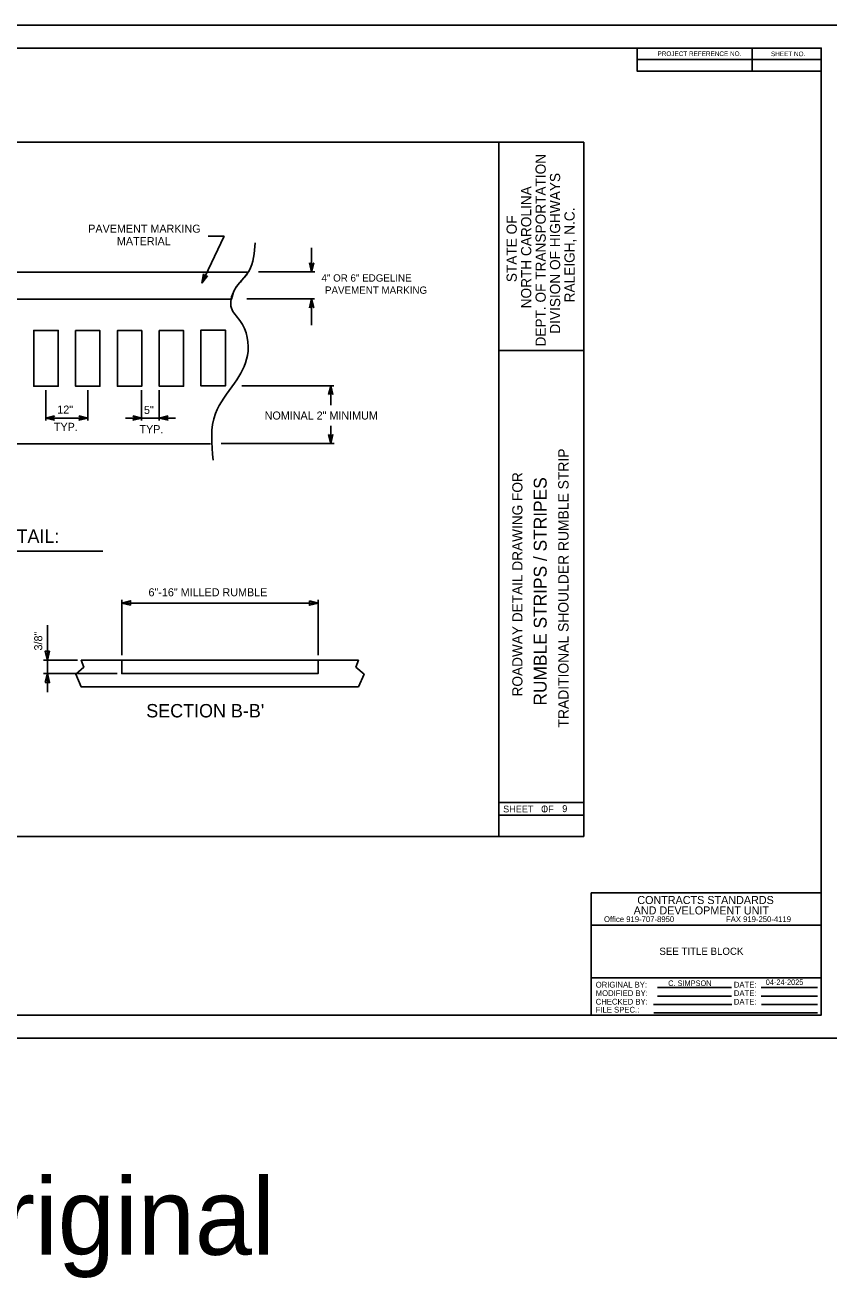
# Model space of a CAD drawing. Extents: x 1994737 to 2001433, y 527447 to 529360.
# Drawn here: x 1995696 to 1996750, y 527488 to 529114 of the extents above; entities that cross this region are included whole.
import ezdxf

# ---------------------------------------------------------------- set-up
doc = ezdxf.new("R2010")
doc.units = 0
for name, color, linetype in [('Default', 7, 'Continuous'), ('GSBWFILL', 7, 'Continuous'), ('Old_Level_1', 7, 'Continuous'), ('Old_Level_40', 7, 'Continuous'), ('Old_Level_60', 7, 'Continuous'), ('Prop Mkg Solid Yel Skip LT', 7, 'Continuous'), ('Prop Sign E Yield Sign Ahead CELL', 7, 'Continuous'), ('Prop Support Two', 7, 'Continuous')]:
    doc.layers.add(name, color=color, linetype=linetype)

# ---------------------------------------------------------------- blocks, each defined once
blk = doc.blocks.new('TERM2')
at = {"layer": 'Default'}
for p, q in [((-6.25, 1.563), (0, 0)), ((-4.687, 0), (-6.25, 1.563)), ((0, 0), (-6.25, -1.563)), ((-6.25, -1.563), (-4.687, 0))]:
    blk.add_line(p, q, dxfattribs=at)
blk = doc.blocks.new('TERM')
at = {"layer": 'Default'}
blk.add_lwpolyline([(-6.25, 1.563), (0, 0), (-6.25, -1.563)], close=True, dxfattribs=at)

msp = doc.modelspace()

# ---------------------------------------------------------------- linework, layer by layer
at = {"layer": 'Default'}
for p, q in [((1995954.6, 528840.3), (1995925.3, 528779.3)), ((1995933.9, 528840.3), (1995954.6, 528840.3)), ((1996068, 528824.8), (1996068, 528793.8)), ((1995178.8, 528793.5), (1995986.2, 528793.5)), ((1995985.9, 528793.5), (1995179.6, 528793.5)), ((1995998.9, 528793.8), (1996072.1, 528793.8)), ((1995201.2, 528758.5), (1995964.5, 528758.5)), ((1995201.7, 528758.5), (1995963.8, 528758.5)), ((1995983.9, 528758.9), (1996071.9, 528758.9)), ((1996068, 528758.8), (1996068, 528724.6)), ((1995723.1, 528640.4), (1995723.1, 528600.7)), ((1995777.4, 528640.4), (1995777.4, 528600.7)), ((1995847.4, 528640.4), (1995847.4, 528600.7)), ((1995870.1, 528640.4), (1995870.1, 528600.7)), ((1995977.2, 528646), (1996096.8, 528646)), ((1996092.8, 528620.9), (1996092.8, 528646)), ((1995722.9, 528604.1), (1995777.4, 528604.1)), ((1995826.6, 528604.1), (1995891.4, 528604.1)), ((1996092.8, 528571.2), (1996092.8, 528594)), ((1995228.8, 528570.4), (1995936.7, 528570.4)), ((1995950.5, 528571.2), (1996097.2, 528571.2)), ((1995534.7, 528431.2), (1995796.9, 528431.2)), ((1995821.5, 528296.3), (1995821.5, 528367.9)), ((1995821.5, 528364), (1996076.6, 528364)), ((1996076.6, 528296.3), (1996076.6, 528367.9)), ((1995725, 528289.8), (1995725, 528335.2)), ((1995764, 528289.8), (1995719.9, 528289.8)), ((1995725, 528272.4), (1995725, 528289.8)), ((1995772.4, 528280.9), (1995761.8, 528271.6)), ((1995772.4, 528280.9), (1995761.8, 528271.6)), ((1995769.1, 528289.8), (1995772.4, 528280.9)), ((1995769.1, 528289.8), (1995772.4, 528280.9)), ((1995821.5, 528289.8), (1995769.1, 528289.8)), ((1995769.1, 528289.8), (1995769.1, 528289.8)), ((1995769.1, 528289.8), (1995772.4, 528280.9)), ((1995772.4, 528280.9), (1995769.1, 528289.8)), ((1995769.1, 528289.8), (1995821.5, 528289.8)), ((1995821.5, 528289.8), (1995821.5, 528272.4)), ((1995821.5, 528272.4), (1995821.5, 528289.8)), ((1995821.5, 528289.8), (1995954.8, 528289.8)), ((1995954.8, 528289.8), (1996128.7, 528289.8)), ((1996076.3, 528289.8), (1996076.3, 528272.4)), ((1996076.3, 528289.8), (1996128.7, 528289.8)), ((1996076.3, 528288.1), (1996076.3, 528289.8)), ((1996076.3, 528272.4), (1996076.3, 528288.1)), ((1996128.7, 528289.8), (1996125.4, 528280.9)), ((1996128.7, 528289.8), (1996125.4, 528280.9)), ((1996125.4, 528280.9), (1996136, 528271.6)), ((1996125.4, 528280.9), (1996136, 528271.6)), ((1995815.7, 528272.4), (1995719.9, 528272.4)), ((1995725, 528272.4), (1995725, 528248.3)), ((1995761.8, 528271.6), (1995769.1, 528255)), ((1995761.8, 528271.6), (1995769.1, 528255)), ((1995821.5, 528272.4), (1995943.7, 528272.4)), ((1995943.7, 528272.4), (1995821.5, 528272.4)), ((1995943.7, 528272.4), (1996076.3, 528272.4)), ((1995943.7, 528272.4), (1996076.3, 528272.4)), ((1996136, 528271.6), (1996128.7, 528255)), ((1996136, 528271.6), (1996128.7, 528255)), ((1995769.1, 528255), (1995949.6, 528255)), ((1995769.1, 528255), (1995949.6, 528255)), ((1995949.6, 528255), (1996128.7, 528255)), ((1996128.7, 528255), (1995949.6, 528255))]:
    msp.add_line(p, q, dxfattribs=at)
for points in [[(1995003.5, 528962), (1996421.2, 528962), (1996421.2, 528061), (1995003.5, 528061)], [(1995924.4, 528718.1), (1995956, 528718.1), (1995956, 528645.7), (1995924.4, 528645.7)], [(1995707.4, 528717.7), (1995739.1, 528717.7), (1995739.1, 528645.3), (1995707.4, 528645.3)], [(1995761.6, 528717.6), (1995793.3, 528717.6), (1995793.3, 528645.2), (1995761.6, 528645.2)], [(1995815.9, 528717.6), (1995847.6, 528717.6), (1995847.6, 528645.2), (1995815.9, 528645.2)], [(1995870.2, 528717.6), (1995901.9, 528717.6), (1995901.9, 528645.2), (1995870.2, 528645.2)], [(1996076.3, 528289.8), (1996128.7, 528289.8), (1996125.4, 528280.9), (1996136, 528271.6), (1996128.7, 528255), (1995769.1, 528255), (1995761.8, 528271.6), (1995772.4, 528280.9), (1995769.1, 528289.8), (1995821.5, 528289.8), (1995821.5, 528272.4), (1996076.3, 528272.4)]]:
    msp.add_lwpolyline(points, close=True, dxfattribs=at)
for points in [[(1995924.4, 528645.7), (1995956, 528645.7), (1995956, 528718.1), (1995924.4, 528718.1), (1995924.4, 528645.7)], [(1995707.4, 528645.3), (1995739.1, 528645.3), (1995739.1, 528717.7), (1995707.4, 528717.7), (1995707.4, 528645.3)], [(1995761.6, 528645.2), (1995793.3, 528645.2), (1995793.3, 528717.6), (1995761.6, 528717.6), (1995761.6, 528645.2)], [(1995815.9, 528645.2), (1995847.6, 528645.2), (1995847.6, 528717.6), (1995815.9, 528717.6), (1995815.9, 528645.2)], [(1995870.2, 528645.2), (1995901.9, 528645.2), (1995901.9, 528717.6), (1995870.2, 528717.6), (1995870.2, 528645.2)]]:
    msp.add_lwpolyline(points, dxfattribs=at)
for points in [[(1995994.6, 528831.6), (1995986.7, 528795.1), (1995967.9, 528770.3), (1995963.9, 528746.6), (1995974.8, 528730.7), (1995984.7, 528685.1), (1995967.9, 528649.5), (1995943.1, 528609.9), (1995940, 528549.3)], [(1995963.8, 528758.5), (1995967.9, 528770.3), (1995969.7, 528773.5), (1995971.9, 528776.4), (1995976.7, 528781.9), (1995981.7, 528787.4), (1995983.9, 528790.4), (1995985.9, 528793.5)]]:
    msp.add_spline(points, degree=3, dxfattribs=at)
at = {"layer": 'GSBWFILL'}
for p, q in [((1996749.7, 529114.1), (1994737.1, 529114.1)), ((1994737.1, 527799.4), (1996749.7, 527799.4))]:
    msp.add_line(p, q, dxfattribs=at)
at = {"layer": 'Old_Level_40'}
for p, q in [((1996639.7, 529084.1), (1996639.7, 529054.3)), ((1996490.3, 529069.2), (1996729.4, 529069.2))]:
    msp.add_line(p, q, dxfattribs=at)
msp.add_lwpolyline([(1996490.3, 529084.2), (1996729.4, 529084.2), (1996729.4, 529054.3), (1996490.3, 529054.3)], close=True, dxfattribs=at)
at = {"layer": 'Old_Level_60'}
for p, q in [((1996729.4, 527988), (1996430.6, 527988)), ((1996430.6, 527988), (1996430.6, 527946.1)), ((1996729.4, 527829.3), (1996729.4, 527988)), ((1996430.6, 527866.7), (1996430.6, 527946.1)), ((1996430.6, 527946.1), (1996729.4, 527946.1)), ((1996729.4, 527877.7), (1996430.6, 527877.7)), ((1996430.6, 527866.7), (1996430.6, 527829.3)), ((1996516.9, 527864.9), (1996612.8, 527864.9)), ((1996651.4, 527864.9), (1996724.4, 527864.9)), ((1996511.7, 527842.8), (1996613.2, 527842.8)), ((1996516.9, 527853.8), (1996612.8, 527853.8)), ((1996651.4, 527853.8), (1996724.4, 527853.8)), ((1996651.9, 527842.8), (1996724.4, 527842.8)), ((1996430.6, 527829.3), (1996729.4, 527829.3)), ((1996512, 527832.3), (1996724.4, 527832.3))]:
    msp.add_line(p, q, dxfattribs=at)
msp.add_lwpolyline([(1996310.8, 528691.7), (1996421.2, 528691.7), (1996421.2, 528962), (1996310.8, 528962), (1996310.8, 528061), (1996421.2, 528061), (1996421.2, 528088.6), (1996310.8, 528088.6), (1996310.8, 528105.2), (1996421.2, 528105.2)], dxfattribs=at)
at = {"layer": 'Prop Sign E Yield Sign Ahead CELL'}
msp.add_lwpolyline([(1996729.4, 529084.2), (1994936.7, 529084.2), (1994936.7, 527829.3), (1996729.4, 527829.3)], close=True, dxfattribs=at)
at = {"layer": 'Prop Support Two'}
msp.add_line((1996749.7, 529114.1), (1996749.7, 529114.1), dxfattribs=at)

# ---------------------------------------------------------------- block references
at = {"layer": 'Default'}
for name, p, xscale, yscale, rotation in [('TERM2', (1996068, 528793.8), 1.8556685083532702, 1.8556685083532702, -89.99999999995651), ('TERM2', (1995925.3, 528779.3), 1.8556685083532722, 1.8556685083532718, -115.63251036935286), ('TERM2', (1996068, 528758.8), 1.8556685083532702, 1.8556685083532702, 90.00000000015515), ('TERM2', (1996092.8, 528646), 1.8556685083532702, 1.8556685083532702, 90.00000000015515), ('TERM2', (1995722.9, 528604.1), 1.8556685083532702, 1.8556685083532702, 179.99999999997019), ('TERM2', (1995777.4, 528604.1), 1.8556685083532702, 1.8556685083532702, -2.9817700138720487e-11), ('TERM2', (1995847.6, 528604.1), 1.8556685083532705, 1.8556685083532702, -0.009516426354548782), ('TERM2', (1995870.2, 528604.1), 1.855668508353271, 1.8556685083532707, -179.75274341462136), ('TERM2', (1996092.8, 528571.2), 1.8556685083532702, 1.8556685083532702, -89.99999999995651), ('TERM', (1995821.5, 528364), 1.8556685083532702, 1.8556685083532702, 179.9999999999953), ('TERM', (1996076.6, 528364), 1.8556685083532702, 1.8556685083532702, -4.686499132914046e-12), ('TERM', (1995725, 528289.8), 1.8556685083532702, 1.8556685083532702, -90.0000000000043), ('TERM', (1995725, 528272.4), 1.8556685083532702, 1.8556685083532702, 89.99999999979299)]:
    msp.add_blockref(name, p, dxfattribs=dict(at, xscale=xscale, yscale=yscale, rotation=rotation))

# ---------------------------------------------------------------- texts
for s, height, rotation, p in [('PAVEMENT MARKING', 10.438, 360, (1995778.1, 528844.6)), ('MATERIAL', 10.44, 360, (1995815.3, 528828.4)), ('4" OR 6" EDGELINE', 9.489, 360, (1996080.8, 528781.1)), ('PAVEMENT MARKING', 9.489, 360, (1996085.3, 528765.3)), ('12"', 10.44, 360, (1995737.9, 528609.8)), ('5"', 10.44, 360, (1995850.4, 528609.3)), ('NOMINAL 2" MINIMUM', 10.438, 360, (1996007, 528602.1)), ('TYP.', 10.44, 360, (1995733.5, 528587.4)), ('TYP.', 10.44, 360, (1995844.6, 528584.4)), ('MILLING DETAIL:', 17.397, 0, (1995553.2, 528442)), ('6"-16" MILLED RUMBLE', 10.438, 0, (1995856.3, 528372.7)), ('3/8"', 10.44, 90.0002, (1995718.4, 528302.4)), ("SECTION B-B'", 17.397, 0, (1995853.4, 528215.5)), ('SHEET 1 - original', 99.727, 0, (1994916, 527518.1))]:
    msp.add_text(s, height=height, rotation=rotation, dxfattribs=at).set_placement(p)
for s, p in [('C. SIMPSON', (1996530.7, 527867)), ('04-24-2025', (1996657.3, 527868.3))]:
    msp.add_text(s, height=7.14, dxfattribs=at).set_placement(p)
at = {"layer": 'Old_Level_1'}
for s, height, p in [('TRADITIONAL SHOULDER RUMBLE STRIP', 13.461, (1996401.4, 528202.4)), ('RUMBLE STRIPS / STRIPES', 16.826, (1996373, 528230.9))]:
    msp.add_text(s, height=height, rotation=90, dxfattribs=at).set_placement(p)
msp.add_text('1      9', height=8.97, dxfattribs=at).set_placement((1996366.5, 528092.6))
at = {"layer": 'Old_Level_60'}
for s, height, rotation, p in [('DEPT. OF TRANSPORTATION', 13.245, 90, (1996371.8, 528696.9)), ('DEPT. OF TRANSPORTATION', 13.245, 90, (1996371.8, 528696.9)), ('DIVISION OF HIGHWAYS', 13.245, 90, (1996390.5, 528713.5)), ('DIVISION OF HIGHWAYS', 13.245, 90, (1996390.5, 528713.5)), ('NORTH CAROLINA', 13.245, 90, (1996353, 528746.4)), ('NORTH CAROLINA', 13.245, 90, (1996353, 528746.4)), ('STATE OF', 13.24, 90, (1996334.2, 528780.4)), ('STATE OF', 13.24, 90, (1996334.2, 528780.4)), ('RALEIGH, N.C.', 13.245, 90, (1996409.3, 528754.2)), ('RALEIGH, N.C.', 13.245, 90, (1996409.3, 528754.2)), ('ROADWAY DETAIL DRAWING FOR', 13.236, 90, (1996341.6, 528242.7)), ('SEE TITLE BLOCK', 9.406, 0.0008, (1996519.3, 527907.3))]:
    msp.add_text(s, height=height, rotation=rotation, dxfattribs=at).set_placement(p)
for s, height, p in [('SHEET   OF', 8.83, (1996316.5, 528092.2)), ('SHEET   OF', 8.83, (1996316.5, 528092.2)), ('AND DEVELOPMENT UNIT', 10.457, (1996485.9, 527959.8)), ('CONTRACTS STANDARDS', 10.457, (1996490.6, 527973.3)), ('Office 919-707-8950', 7.469, (1996447.4, 527949.9)), ('FAX 919-250-4119', 7.469, (1996605.7, 527949.9)), ('ORIGINAL BY:', 7.469, (1996436.6, 527864.9)), ('DATE:', 7.47, (1996615.9, 527864.9)), ('MODIFIED BY:', 7.469, (1996436.6, 527853.9)), ('DATE:', 7.47, (1996615.9, 527853.9)), ('CHECKED BY:', 7.469, (1996436.6, 527842.8)), ('FILE SPEC.:', 7.469, (1996436.6, 527832.4)), ('DATE:', 7.47, (1996615.9, 527842.8))]:
    msp.add_text(s, height=height, dxfattribs=at).set_placement(p)
at = {"layer": 'Prop Mkg Solid Yel Skip LT'}
for s, height, p in [('PROJECT REFERENCE NO.', 5.976, (1996516.9, 529073.9)), ('SHEET NO.', 5.98, (1996664.1, 529073.7))]:
    msp.add_text(s, height=height, dxfattribs=at).set_placement(p)

doc.saveas('drawing.dxf')
